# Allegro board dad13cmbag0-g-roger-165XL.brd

Outline 225 x 71 mm; copper layers: TOP, GND, IN1, IN2, SGND1, SVCC, IN3, IN4, GND2, BOTTOM. Coordinates in mm from the lower left corner of the outline.
Outline path: 0,6.1 0,17.14 arc(0.54,17.85) 1.06,18.58 arc(1.59,18.97) 2.26,18.94 arc(4.75,19.83) 4.19,22.41 arc(3.81,22.96) 3.87,23.62 arc(5.79,29.62) 6.44,35.9 6.44,59.4 arc(6.59,59.75) 6.94,59.9 10.44,59.9 10.44,68.4 arc(10.59,68.75) 10.94,68.9 14.54,68.9 arc(15.07,68.75) 15.44,68.33 arc(17.7,66.9) 19.96,68.33 arc(20.33,68.75) 20.86,68.9 63.6,68.9 65.7,71 73.7,71 75.8,68.9 118.54,68.9 arc(119.07,68.75) 119.44,68.33 arc(121.7,66.9) 123.96,68.33 arc(124.33,68.75) 124.86,68.9 204.9,68.9 206.41,70.41 arc(206.73,70.62) 207.11,70.7 209.71,70.7 arc(209.95,70.58) 209.99,70.32 arc(211.1,68.85) 212.21,70.32 arc(212.25,70.58) 212.49,70.7 213.88,70.7 arc(214.13,70.67) 214.37,70.57 arc(215.59,70.26) 216.8,70.57 arc(217.04,70.67) 217.29,70.7 222.8,70.7 arc(223.15,70.55) 223.3,70.2 223.3,69.9 arc(223.45,69.55) 223.8,69.4 224.5,69.4 arc(224.85,69.25) 225,68.9 225,67.25 arc(224.71,66.54) 224,66.25 215.05,66.25 214.98,66.24 214.92,66.21 214.87,66.17 214.83,66.12 214.81,66.06 214.8,66 214.81,65.93 214.83,65.87 214.87,65.82 214.93,65.78 214.99,65.76 215.05,65.75 215.05,58.05 214.98,58.04 214.92,58.01 214.87,57.97 214.83,57.92 214.81,57.86 214.8,57.8 214.81,57.73 214.83,57.67 214.87,57.62 214.93,57.58 214.99,57.56 215.05,57.55 224,57.55 arc(224.71,57.25) 225,56.55 225,53.75 214.64,53.75 214.64,54.25 212.4,54.25 212.4,39.15 214.64,39.15 214.64,39.65 223.3,39.65 223.3,34.9 224,34.9 224.4,34.5 224.4,30 225,29.4 225,27.2 224.5,27.2 224.5,26.2 225,26.2 225,23.6 224.5,23.6 224.5,22.6 225,22.6 225,20 224.5,20 224.5,19 225,19 225,16.4 224.5,16.4 224.5,15.4 225,15.4 225,12.85 224.5,12.85 224.5,11.85 225,11.85 225,9.7 arc(224.71,8.99) 224,8.7 214.2,8.7 arc(213.85,8.85) 213.7,9.2 213.7,10.83 arc(213.8,11.12) 214.05,11.3 arc(214.51,13.21) 212.6,12.75 arc(212.42,12.5) 212.13,12.4 210.9,12.4 arc(210.55,12.25) 210.4,11.9 210.4,8.4 arc(209.52,6.28) 207.4,5.4 129.62,5.4 arc(129.19,5.5) 128.84,5.77 arc(126.9,6.7) 124.96,5.77 arc(124.61,5.5) 124.18,5.4 54.5,5.4 arc(53.79,5.11) 53.5,4.4 53.5,2.8 arc(50.7,0) 47.9,2.8 47.9,4.4 arc(47.61,5.11) 46.9,5.4 15.32,5.4 arc(14.89,5.5) 14.54,5.77 arc(12.6,6.7) 10.66,5.77 arc(10.31,5.5) 9.88,5.4 9.5,5.4 8.5,5.1 1,5.1 arc(0.29,5.39) 0,6.1

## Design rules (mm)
constraint set DEFAULT: min track width 0.127
net group DFP-S4(4)W4(8)-1234: nets M_A_CLKN0 M_A_CLKP0
net group DFP-S4(4)W4(8)-T1234B: nets M_B_CLKN0 M_B_CLKP0
net group DFP-S4(5.5)W4(3.5)-T124B: nets CLK_PCIE_WLANN CLK_PCIE_WLANP
net group DFP-S6W10-T1234B: nets VCCSENSE VSSSENSE
net group DFP-S10(40)W30(40)-T1B: nets AUD_SPK_R+ AUD_SPK_R-
net group DFP-S10W5(3.5)-T123: nets I2C0_SCL_DSP I2C0_SDA_DSP
net group DFP-S10W10-T124B: nets REM_DIODE1_N REM_DIODE1_P
net group W3(3.5)-T1234B: nets M_A_ODT M_B_ODT
net group DFP-S3.5(4.5)W4.5(3.5)-T124B: nets PCIE_RXN3 PCIE_RXP3 PCIE_TXN3 PCIE_TXN3_C PCIE_TXP3 PCIE_TXP3_C USB3.0_RX1+ USB3.0_RX1- USB3.0_TX1+ USB3.0_TX1+_C USB3.0_TX1- USB3.0_TX1-_C
net group DFP-S4.5(4)W8.5(6.5)-T1234B: nets M_A_DQSN0 M_A_DQSN1 M_A_DQSN2 M_A_DQSN3 M_A_DQSN4 M_A_DQSN5 M_A_DQSN6 M_A_DQSN7 M_A_DQSP0 M_A_DQSP1 M_A_DQSP2 M_A_DQSP3 M_A_DQSP4 M_A_DQSP5 M_A_DQSP6 M_A_DQSP7 M_B_DQSN0 M_B_DQSN1 M_B_DQSN2 M_B_DQSN3 M_B_DQSN4 M_B_DQSN5 M_B_DQSN6 M_B_DQSN7 M_B_DQSP0 M_B_DQSP1 M_B_DQSP2 M_B_DQSP3 M_B_DQSP4 M_B_DQSP5 M_B_DQSP6 M_B_DQSP7
net group DFP-S5(8)W5.5(5)-T124B: nets AUX_SINK_N_R AUX_SINK_P_R EDP_AUXN EDP_AUXN_C EDP_AUXN_R EDP_AUXP EDP_AUXP_C EDP_AUXP_R EDP_TXN0_C EDP_TXN0_R EDP_TXN1 EDP_TXN1_C EDP_TXN1_R EDP_TXP0_C EDP_TXP0_R EDP_TXP1 EDP_TXP1_C EDP_TXP1_R INT_AUX_SINKN INT_AUX_SINKP INT_DP_TXN0 INT_DP_TXN1 INT_DP_TXN1_C INT_DP_TXN2 INT_DP_TXN3 INT_DP_TXN3_C INT_DP_TXP0 INT_DP_TXP1 INT_DP_TXP2 INT_DP_TXP3 INT_DP_TXP3_C
net group DFP-S5.5(6)W6.5(4.5)-T1234B: nets N123302860 N123302864 N123305105 N123305107
net group DFP-S5.5(9)W5(4.5)-T124B: nets SATA_RXN2_C SATA_RXP2_C SATA_TXN2_C SATA_TXP2_C USB3.0_RX2+ USB3.0_RX2- USB3.0_TX2+ USB3.0_TX2- USBP0+ USBP0+_L USBP0+_R USBP0- USBP0-_L USBP0-_R USBP1+ USBP1- USBP2+ USBP2+_R USBP2- USBP2-_R USBP4+ USBP4+_L USBP4- USBP4-_L USBP5+ USBP5+_L USBP5- USBP5-_L
net group DFP-S10W5(3.5)-T124B: nets DMIC_CLK DMIC_DATA PS/2_CLK_TPAD PS/2_DAT_TPAD SMB_CLK_ME1 SMB_DATA_ME1 SMBCLK SMBCLK0 SMBCLK0_B SMBCLK0_P SMBCLK1 SMBCLK3 SMBDAT0 SMBDAT0_B SMBDAT0_P SMBDAT1 SMBDAT3 SMBDATA TOUCH_PAD_CLK TOUCH_PAD_CLK_R TOUCH_PAD_DAT TOUCH_PAD_DAT_R TP_CLK TP_DATA
net group DFP-S10W5-TB: nets XTAL24_DSP_IN XTAL24_DSP_OUT XTAL24_IN XTAL24_OUT
net group T14B: nets USB_BIAS
net group T124B: nets SM_RCOMP_0 SM_RCOMP_1 SM_RCOMP_2
net group T1234B: nets +1.2V_SWR +1.2V_SWR_L +3.3V_DEEP_SLEEP_OFF +3.3V_RTC_LDO +DSP_VREF_IN +DVDD-25-LDO-O +DVDIO +LCDVCC +LED_BL +RTC_1 +RTC_CELL +SMDDR_VREF_CA +SMDDR_VREF_DQA +USB0_SIDE_PWR +V1.05DX_MODPHY +V1.05S_APLLOPI +V1.05S_ASATA3PLL +V1.05S_AUSB3PLL +V1.05S_AXCK_DCB +V1.05S_AXCK_LCPLL +V1.05S_VCCST +V3.3DX_1.5DX_AUDIO +V3.3DX_AUDIO +V3.3DX_CAMERA +V3.3DX_NGFF_WLAN +V3.3DX_SSD +V3.3S_1.8S_LPSS_SDIO +V5DX_AUDIO +VCCIO_OUT +VCCIOA_OUT PCIE_IREF PCIE_RCOMP SATA_RCOMP SM_VREF_CA SM_VREF_DQ0 SM_VREF_DQ1
net group TB: nets EDP_COMP PCH_OPIRCOMP PROC_OPI_COMP SATA_IREF
net group W3(6.5)-T1234B: nets M_A_A2 M_A_A5 M_A_A6 M_A_A8 M_A_A10 M_A_A11 M_A_A13 M_A_BS1 M_A_CKE0 M_A_CKE1 M_B_A2 M_B_A5 M_B_A6 M_B_A8 M_B_A10 M_B_A11 M_B_A12 M_B_A13 M_B_BS1 M_B_CKE0 M_B_CKE1
net group W5(3.5)-T123: nets SMC_EXTSMI_N
net group W5(3.5)-T124B: nets ACZ_SPKR APWROK BEEP BT_PCMCLK BT_PCMFR1 BT_PCMIN BT_PCMOUT BUF_PLT_RST# CLK_33M_TPM_TPM CLKDVCOM DP_UTIL DPWROK_R DSP_BITCLK DSP_BITCLK_R DSP_RST# DSP_SDIN0 DSP_SDOUT DSP_SYNC DSWVRMEN EC_SPI_CS# EC_SPI_DIN EC_SPI_DO EC_SPI_SLK H_CPU_SVIDALRT_N H_CPUPWRGD H_PROCHOT# H_PROCHOT#_EC HDA_BITCLK HDA_BITCLK_CODEC HDA_BITCLK_DSP HDA_BITCLK_R HDA_RST# HDA_RST#_CODEC HDA_RST#_DSP HDA_RST#_R HDA_SDIN0 HDA_SDIN0_CODEC HDA_SDIN0_DSP HDA_SDOUT HDA_SDOUT_CODEC HDA_SDOUT_DSP HDA_SDOUT_R HDA_SYNC HDA_SYNC_CODEC HDA_SYNC_DSP HDA_SYNC_R HWPG I2S_BCLK_OUT I2S_SDI_IN I2S_SDO_OUT I2S_SFRM_OUT IMVP7_PROCHOT# INT_DP_HPD INT_DP_HPD_R LCD_PWM LPC_CLK_0 LPC_CLK_1 LPC_CLK_DEBUG LPC_CLK_DEBUG_R LPC_CLK_EC LPC_CLK_TPM LPC_LAD0 LPC_LAD0_TPM LPC_LAD1 LPC_LAD1_TPM LPC_LAD2 LPC_LAD2_TPM LPC_LAD3 LPC_LAD3_TPM LPC_LFRAME# LPC_LFRAME#_TPM ME_SUS_PWR_ACK PCH_INTVRMEN PCH_PWROK PCH_SPI_CLK PCH_SPI_CS0# PCH_SPI_IO2 PCH_SPI_IO3 PCH_SPI_SI PCH_SPI_SO PCH_THRMTRIP# PCIE_WAKE# PCIE_WAKE#_R PECI_EC PECI_EC_R PLTRST# RSMRST# RTC_RST# SDIO_CMD SDIO_D0 SDIO_D1 SDIO_D2 SDIO_D3 SIO_PWRBTN# SIO_RCIN# SIO_SLP_LAN# SIO_WAKE_SCI# SM_INTRUDER# SPI_CS# SPI_SCK SPI_SI SPI_SO SRTC_RST# SYS_PWROK SYS_PWROK_R UART1_CTS UART1_CTS_R UART1_RTS UART1_RTS_R UART1_RX UART1_RX_R UART1_TX UART1_TX_R USB3_P0_EN USB3_P1_EN VCCST_PWRGD# VCCST_PWRGD_L VR_SVID_ALERT# VR_SVID_CLK VR_SVID_DATA XDP_TCK0 XDP_TCK1
net group W5(3.5)-T1234B: nets CFG0 CFG1 CFG2 CFG3 CFG4 CFG5 CFG6 CFG7 CFG8 CFG9 CFG10 CFG11 CFG12 CFG13 CFG14 CFG15 IRQ_SERIRQ NOA_RCOMP SIO_EXT_SCI# SIO_SLP_A# SIO_SLP_S3# SIO_SLP_S5# SUSACK# SUSACK#_R SYS_PWR_SW# SYS_RESET# SYS_SHDN# TD_IREF THERM_ALERT# THERM_STP# USB2_CAM_PWR_EN USB2_CAM_PWR_EN_R XDP_BPM0_R XDP_BPM1_R XDP_BPM2_R XDP_BPM3_R XDP_BPM4_R XDP_BPM5_R XDP_BPM6_R XDP_BPM7_R XDP_PRDY_N XDP_PREQ_N XDP_TDI_CPU XDP_TDO_CPU XDP_TMS_CPU XDP_TRST_CPU_N
net group W8.5(6)-T1234B: nets M_A_DQ0 M_A_DQ1 M_A_DQ2 M_A_DQ3 M_A_DQ4 M_A_DQ5 M_A_DQ6 M_A_DQ7 M_A_DQ8 M_A_DQ9 M_A_DQ10 M_A_DQ11 M_A_DQ12 M_A_DQ13 M_A_DQ14 M_A_DQ15 M_A_DQ16 M_A_DQ17 M_A_DQ18 M_A_DQ19 M_A_DQ20 M_A_DQ21 M_A_DQ22 M_A_DQ23 M_A_DQ24 M_A_DQ25 M_A_DQ26 M_A_DQ27 M_A_DQ28 M_A_DQ29 M_A_DQ30 M_A_DQ31 M_A_DQ32 M_A_DQ33 M_A_DQ34 M_A_DQ35 M_A_DQ36 M_A_DQ37 M_A_DQ38 M_A_DQ39 M_A_DQ40 M_A_DQ41 M_A_DQ42 M_A_DQ43 M_A_DQ44 M_A_DQ45 M_A_DQ46 M_A_DQ47 M_A_DQ48 M_A_DQ49 M_A_DQ50 M_A_DQ51 M_A_DQ52 M_A_DQ53 M_A_DQ54 M_A_DQ55 M_A_DQ56 M_A_DQ57 M_A_DQ58 M_A_DQ59 M_A_DQ60 M_A_DQ61 M_A_DQ62 M_A_DQ63 M_B_DQ0 M_B_DQ1 M_B_DQ2 M_B_DQ3 M_B_DQ4 M_B_DQ5 M_B_DQ6 M_B_DQ7 M_B_DQ8 M_B_DQ9 M_B_DQ10 M_B_DQ11 M_B_DQ12 M_B_DQ13 M_B_DQ14 M_B_DQ15 M_B_DQ16 M_B_DQ17 M_B_DQ18 M_B_DQ19 M_B_DQ20 M_B_DQ21 M_B_DQ22 M_B_DQ23 M_B_DQ24 M_B_DQ25 M_B_DQ26 M_B_DQ27 M_B_DQ28 M_B_DQ29 M_B_DQ30 M_B_DQ31 M_B_DQ32 M_B_DQ33 M_B_DQ34 M_B_DQ35 M_B_DQ36 M_B_DQ37 M_B_DQ38 M_B_DQ39 M_B_DQ40 M_B_DQ41 M_B_DQ42 M_B_DQ43 M_B_DQ44 M_B_DQ45 M_B_DQ46 M_B_DQ47 M_B_DQ48 M_B_DQ49 M_B_DQ50 M_B_DQ51 M_B_DQ52 M_B_DQ53 M_B_DQ54 M_B_DQ55 M_B_DQ56 M_B_DQ57 M_B_DQ58 M_B_DQ59 M_B_DQ60 M_B_DQ61 M_B_DQ62 M_B_DQ63
net group W9(6.5)-T1234B: nets M_A_A0 M_A_A1 M_A_A3 M_A_A4 M_A_A7 M_A_A9 M_A_A12 M_A_A14 M_A_A15 M_A_BS0 M_A_BS2 M_A_CAS# M_A_CS#0 M_A_CS#1 M_A_RAS# M_A_WE# M_B_A0 M_B_A1 M_B_A3 M_B_A4 M_B_A7 M_B_A9 M_B_A14 M_B_A15 M_B_BS0 M_B_BS2 M_B_CAS# M_B_CS#0 M_B_CS#1 M_B_RAS# M_B_WE# N123302883 N123302892 N123305111 N123305113

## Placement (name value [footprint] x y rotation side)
C1  10u/6.3v_6  [CC0603]  56.35 66.37 270 top
C2  47u/10v_8  [CC0805]  54.57 66.12 270 top
C3  0.1u/16v_4  [CC0402]  134.33 65.87 270 top
C4  0.1u/16v_4  [CC0402]  135.34 65.87 270 top
C5  1u/6.3v_4  [CC0402]  136.36 65.87 270 top
C6  0.1u/16v_4  [CC0402]  137.37 65.87 270 top
C7  0.1u/16v_4  [CC0402]  208.24 63.96 180 top
C8  100p/50v_4  [CC0402]  128.31 65.28 270 top
C9  *0.1u/10v_4_nc  [CC0402]  128.86 63.61 180 top
C10  0.1u/16v_4  [CC0402]  208.24 62.95 180 top
C11  47u/10v_8  [CC0805]  56.35 62.69 270 top
C12  10u/6.3v_6  [CC0603]  58 62.44 270 top
C13  0.1u/16v_4  [CC0402]  208.24 61.93 180 top
C14  0.1u/16v_4  [CC0402]  159.09 61.42 270 top
C15  0.1u/16v_4  [CC0402]  123.33 61.17 90 top
C16  0.1u/16v_4  [CC0402]  208.24 60.91 180 top
C17  1u/6.3v_4  [CC0402]  66.76 60.28 0 top
C18  1u/6.3v_4  [CC0402]  68.92 59.77 90 top
C19  1u/6.3v_4  [CC0402]  70.27 58.5 90 top
C20  0.1u/16v_4  [CC0402]  208.24 59.9 180 top
C21  22u/6.3v_6  [CC0603]  43.14 59.52 270 top
C22  22u/6.3v_6  [CC0603]  44.41 59.52 270 top
C23  22u/6.3v_6  [CC0603]  46.7 59.52 270 top
C24  22u/6.3v_6  [CC0603]  47.97 59.52 270 top
C25  22u/6.3v_6  [CC0603]  49.24 59.52 270 top
C26  100p/50v_4  [CC0402]  50.38 59.52 270 top
C27  10u/6.3v_6  [CC0603]  51.52 59.52 270 top
C28  22u/6.3v_6  [CC0603]  52.69 59.52 270 top
C29  22u/6.3v_6  [CC0603]  53.86 59.52 270 top
C30  10u/6.3v_6  [CC0603]  56.04 59.52 270 top
C31  22u/6.3v_6  [CC0603]  57.21 59.52 270 top
C32  22u/6.3v_6  [CC0603]  58.38 59.52 270 top
C33  22u/6.3v_6  [CC0603]  59.55 59.52 270 top
C34  10u/6.3v_6  [CC0603]  61.76 59.52 270 top
C35  22u/6.3v_6  [CC0603]  62.93 59.52 270 top
C36  100p/50v_4  [CC0402]  54.95 59.39 270 top
C37  100p/50v_4  [CC0402]  60.64 59.39 270 top
C38  100p/50v_4  [CC0402]  45.55 59.26 270 top
C39  1u/6.3v_4  [CC0402]  131.91 59.14 270 top
C40  1u/6.3v_4  [CC0402]  65.11 59.14 90 top
C41  2200p/50v_4  [CC0402]  150.45 58.37 90 top
C42  2200p/50v_4  [CC0402]  156.55 58.37 270 top
C43  0.1u/16v_4  [CC0402]  208.24 58.88 180 top
C44  0.1u/16v_4  [CC0402]  188.55 57.61 90 top
C45  0.1u/16v_4  [CC0402]  144.87 57.51 0 top
C46  22u/6.3v_6  [CC0603]  41.74 57.23 0 top
C47  1u/6.3v_4  [CC0402]  66.63 56.85 270 top
C48  10u/6.3v_6  [CC0603]  71.71 56.85 270 top
C49  22u/6.3v_6  [CC0603]  73.62 56.85 180 top
C50  10u/6.3v_6  [CC0603]  89.88 56.85 90 top
C51  47u/10v_8  [CC0805]  91.53 56.72 90 top
C52  22u/6.3v_6  [CC0603]  65.36 56.47 270 top
C53  0.1u/16v_4  [CC0402]  70.32 56.47 270 top
C54  0.1u/16v_4  [CC0402]  203.79 56.34 270 top
C55  0.1u/16v_4  [CC0402]  204.94 56.34 270 top
C56  0.1u/16v_4  [CC0402]  205.95 56.34 270 top
C57  22u/6.3v_6  [CC0603]  41.74 55.96 0 top
C58  1u/6.3v_4  [CC0402]  73.49 55.71 180 top
C59  22u/6.3v_6  [CC0603]  41.74 54.69 0 top
C60  1u/6.3v_4  [CC0402]  73.49 54.69 180 top
C61  1u/6.3v_4  [CC0402]  75.78 54.44 180 top
C62  10u/6.3v_6  [CC0603]  89.49 53.8 90 top
C63  0.1u/16v_4  [CC0402]  198.54 53.8 90 top
C64  1u/6.3v_4  [CC0402]  73.49 53.67 180 top
C65  22u/6.3v_6  [CC0603]  41.74 53.42 0 top
C66  47u/10v_8  [CC0805]  91.15 53.29 90 top
C67  0.1u/16v_4  [CC0402]  187.16 52.79 180 top
C68  1u/6.3v_4  [CC0402]  73.49 52.66 180 top
C69  0.1u/16v_4  [CC0402]  131.15 52.53 0 top
C70  22u/6.3v_6  [CC0603]  41.74 52.15 0 top
C71  0.1u/16v_4  [CC0402]  197.83 52.02 0 top
C72  0.1u/50v_6  [CC0603]  200.29 52.02 0 top
C73  22u/6.3v_6  [CC0603]  75.91 51.9 0 top
C74  *100p_nc  [CC0402]  52.71 51.82 270 top
C75  0.1u/50v_6  [CC0603]  203.54 51.26 90 top
C76  22u/6.3v_6  [CC0603]  41.74 50.88 0 top
C77  0.1u/16v_4  [CC0402]  192.49 50.88 0 top
C78  1u/6.3v_4  [CC0402]  75.65 50.75 180 top
C79  0.1u/16v_4  [CC0402]  73.49 50.5 0 top
C80  10u/6.3v_6  [CC0603]  89.49 50.12 270 top
C81  47u/10v_8  [CC0805]  91.15 49.86 270 top
C82  0.1u/16v_4  [CC0402]  135.47 49.86 90 top
C83  0.01u/25v_4  [CC0402]  170.14 49.86 180 top
C84  22u/6.3v_6  [CC0603]  41.74 49.61 0 top
C85  22u/6.3v_6  [CC0603]  75.91 49.61 0 top
C86  1u/6.3v_4  [CC0402]  73.49 49.48 0 top
C87  100u/6.3v/3216  [CC3216-0_9H]  34.38 49.36 0 top
C88  10u/6.3v_6  [CC0603]  202.14 48.98 270 top
C89  0.01u/25v_4  [CC0402]  170.14 48.72 180 top
C90  0.1u/16v_4  [CC0402]  203.29 48.72 270 top
C91  1u/6.3v_4  [CC0402]  73.87 48.47 180 top
C92  22u/6.3v_6  [CC0603]  41.74 48.34 0 top
C93  22u/6.3v_8  [CC0805]  206.97 47.71 180 top
C94  2200p/50v_4  [CC0402]  150.84 47.71 180 top
C95  0.1u/16v_4  [CC0402]  154.77 47.71 180 top
C96  1u/6.3v_4  [CC0402]  73.87 47.45 180 top
C97  *4.7u/6.3v_6_nc  [CC0603]  195.67 47.2 180 top
C98  22u/6.3v_6  [CC0603]  41.74 47.07 0 top
C99  0.1u/16v_4  [CC0402]  76.67 46.94 90 top
C100  0.1u/16v_4  [CC0402]  150.84 46.69 180 top
C101  2200p/50v_4  [CC0402]  154.77 46.69 180 top
C102  0.01u/25v_4  [CC0402]  170.27 46.69 0 top
C103  1u/6.3v_4  [CC0402]  68.67 46.56 270 top
C104  1u/6.3v_4  [CC0402]  69.68 46.56 90 top
C105  1u/6.3v_4  [CC0402]  70.7 46.56 270 top
C106  1u/6.3v_4  [CC0402]  71.71 46.56 90 top
C107  0.1u/10v_4  [CC0402]  195.92 45.93 180 top
C108  0.1u/16v_4  [CC0402]  84.97 45.67 90 top
C109  0.1u/16v_4  [CC0402]  85.99 45.67 90 top
C110  100u/6.3v/3216  [CC3216-0_9H]  40.73 45.55 180 top
C111  0.01u/25v_4  [CC0402]  170.27 45.55 0 top
C112  1u/6.3v_4  [CC0402]  65.34 45.42 90 top
C113  1u/6.3v_4  [CC0402]  67.37 45.42 90 top
C114  10u/6.3v_6  [CC0603]  51.27 41.86 180 top
C115  2.2u/6.3v_6  [CC0603]  53.68 44.15 90 top
C116  2.2u/6.3v_6  [CC0603]  56.6 45.29 90 top
C117  10u/6.3v_6  [CC0603]  53.55 36.91 0 top
C118  10u/6.3v_6  [CC0603]  58 35.51 180 top
C119  1u/6.3v_4  [CC0402]  77.3 44.53 90 top
C120  0.1u/16v_4  [CC0402]  68.54 44.2 270 top
C121  1u/6.3v_4  [CC0402]  69.56 44.2 270 top
C122  1u/6.3v_4  [CC0402]  70.57 44.2 270 top
C123  10u/6.3v_6  [CC0603]  71.84 44.05 270 top
C124  10p/50v_4  [CC0402]  103.34 43.64 270 top
C125  *100p_nc  [CC0402]  195.29 43.51 0 top
C126  0.1u/16v_4  [CC0402]  12.74 42.91 0 top
C127  22u/6.3v_8  [CC0805]  207.1 42.19 0 top
C128  18p/50v_4  [CC0402]  109.05 41.86 0 top
C129  18p/50v_4  [CC0402]  111.08 41.86 0 top
C130  *100p_nc  [CC0402]  198.08 41.36 270 top
C131  *100p_nc  [CC0402]  199.1 41.36 270 top
C132  2200p/50v_4  [CC0402]  11.82 41.33 90 top
C133  10p/50v_4  [CC0402]  105.5 41.23 270 top
C134  4.7u/6.3v_4  [CC0402]  112.86 41.1 270 top
C135  0.1u/16v_4  [CC0402]  113.88 41.1 270 top
C136  10u/6.3v_6  [CC0603]  58 38.31 180 top
C137  10p/50v_4  [CC0402]  106.51 40.97 270 top
C138  10p/50v_4  [CC0402]  107.53 40.97 270 top
C139  0.1u/16v_4  [CC0402]  96.86 39.32 0 top
C140  *0.1u/10v_4_nc  [CC0402]  92.54 38.94 90 top
C141  10u/6.3v_6  [CC0603]  112.02 38.69 270 top
C142  *0.1u/25v_6_nc  [CC0603]  113.17 38.69 90 top
C143  0.1u/16v_4  [CC0402]  114.26 38.36 270 top
C144  4.7u/6.3v_4  [CC0402]  96.86 38.31 0 top
C145  0.047u/10v_4  [CC0402]  180.17 37.51 180 top
C146  0.1u/16v_4  [CC0402]  100.8 37.42 0 top
C147  1u/6.3v_4  [CC0402]  161.48 37.06 270 top
C148  10u/6.3v_6  [CC0603]  98.38 37.16 0 top
C149  0.047u/10v_4  [CC0402]  180.17 36.5 180 top
C150  0.1u/16v_4  [CC0402]  100.8 36.02 0 top
C151  0.1u/16v_4  [CC0402]  112.23 36.02 270 top
C152  10u/6.3v_6  [CC0603]  113.62 35.89 270 top
C153  4.7u/6.3v_6  [CC0603]  179.92 35.35 180 top
C154  10u/6.3v_6  [CC0603]  97.75 35.26 270 top
C155  10u/6.3v_6  [CC0603]  99.02 35.26 270 top
C156  47p/50v_4  [CC0402]  138.52 34.75 90 top
C157  0.1u/16v_4  [CC0402]  113.8 34.09 0 top
C158  0.1u/16v_4  [CC0402]  112.15 33.58 90 top
C159  0.1u/10v_4  [CC0402]  170.52 32.6 0 top
C160  0.1u/16v_4  [CC0402]  112.66 31.93 180 top
C161  1u/6.3v_4  [CC0402]  71.71 31.35 90 top
C162  1u/6.3v_4  [CC0402]  75.55 31.35 90 top
C163  1u/6.3v_4  [CC0402]  198.79 31.32 90 top
C164  4.7u/6.3v_4  [CC0402]  112.66 30.92 180 top
C165  0.1u/16v_4  [CC0402]  101.31 30.89 0 top
C166  4.7u/6.3v_4  [CC0402]  102.7 29.8 0 top
C167  0.1u/16v_4  [CC0402]  191.35 19.89 270 top
C168  2200p/50v_4  [CC0402]  15.71 19.64 270 top
C169  *100p_nc  [CC0402]  16.85 19.64 270 top
C170  0.047u/10v_4  [CC0402]  32.6 18.24 0 top
C171  0.047u/10v_4  [CC0402]  76.54 17.99 180 top
C172  0.047u/10v_4  [CC0402]  44.79 17.35 180 top
C173  0.047u/10v_4  [CC0402]  64.22 17.48 0 top
C174  0.047u/10v_4  [CC0402]  20.25 17.48 0 top
C175  0.047u/10v_4  [CC0402]  53.68 17.86 0 top
C176  0.047u/10v_4  [CC0402]  99.91 17.58 180 top
C177  0.047u/10v_4  [CC0402]  88.48 16.72 90 top
C178  1u/6.3v_4  [CC0402]  86.07 12.27 180 top
C179  0.047u/10v_4  [CC0402]  61.05 16.08 0 top
C180  1u/6.3v_4  [CC0402]  219.16 16.08 180 top
C181  0.047u/10v_4  [CC0402]  83.4 13.54 180 top
C182  10u/6.3v_6  [CC0603]  68.29 10.62 0 top
C183  1u/6.3v_4  [CC0402]  85.68 7.57 90 top
C184  0.047u/10v_4  [CC0402]  26.63 14.69 0 top
C185  0.047u/10v_4  [CC0402]  39.08 13.92 90 top
C186  0.047u/10v_4  [CC0402]  51.9 13.92 180 top
C187  0.047u/10v_4  [CC0402]  70.95 12.65 0 top
C188  1u/6.3v_4  [CC0402]  40.98 19 270 top
C189  1u/6.3v_4  [CC0402]  39.58 10.88 180 top
C190  0.047u/10v_4  [CC0402]  95.08 13.8 90 top
C191  0.047u/10v_4  [CC0402]  16.37 12.98 90 top
C192  1u/6.3v_4  [CC0402]  71.08 9.22 0 top
C193  1u/6.3v_4  [CC0402]  67.14 14.3 270 top
C194  1u/6.3v_4  [CC0402]  32.55 14.66 180 top
C195  1u/6.3v_4  [CC0402]  27.14 17.48 0 top
C196  *0.1u/25v_6_nc  [CC0603]  103.08 11.89 0 top
C197  1u/6.3v_4  [CC0402]  70.95 10.49 0 top
C198  1u/6.3v_4  [CC0402]  86.07 10.24 180 top
C199  1u/6.3v_4  [CC0402]  26.88 7.83 90 top
C200  10u/6.3v_6  [CC0603]  25.23 7.95 90 top
C201  1u/6.3v_4  [CC0402]  81.24 16.59 180 top
C202  1u/6.3v_4  [CC0402]  70.95 11.51 0 top
C203  1u/6.3v_4  [CC0402]  39.58 8.84 180 top
C204  1u/6.3v_4  [CC0402]  26.63 13.54 0 top
C205  *10u/6.3v_6_nc  [CC0603]  87.21 7.83 90 top
C206  1u/6.3v_4  [CC0402]  26.88 11.26 0 top
C207  1u/6.3v_4  [CC0402]  78.83 26.5 0 bottom
C208  1u/6.3v_4  [CC0402]  90.13 26.5 0 bottom
C209  *10u/6.3v_6_nc  [CC0603]  42.25 18.75 270 top
C210  1u/6.3v_4  [CC0402]  36.03 27.13 270 bottom
C211  1u/6.3v_4  [CC0402]  74.25 7.7 90 bottom
C212  1u/6.3v_4  [CC0402]  102.07 16.34 90 bottom
C213  1u/6.3v_4  [CC0402]  31.96 27.13 270 bottom
C214  1u/6.3v_4  [CC0402]  80.99 26.5 180 bottom
C215  1u/6.3v_4  [CC0402]  85.3 26.5 180 bottom
C216  1u/6.3v_4  [CC0402]  13.17 9.22 0 bottom
C217  1u/6.3v_4  [CC0402]  44.03 7.83 90 bottom
C218  1u/6.3v_4  [CC0402]  85.68 7.83 90 bottom
C219  1u/6.3v_4  [CC0402]  91.53 7.83 90 bottom
C220  1u/6.3v_4  [CC0402]  94.45 26.5 180 bottom
C221  1u/6.3v_4  [CC0402]  83.14 26.5 180 bottom
C222  1u/6.3v_4  [CC0402]  67.78 26.62 180 bottom
C223  1u/6.3v_4  [CC0402]  96.61 26.5 0 bottom
C224  1u/6.3v_4  [CC0402]  34 27.13 270 bottom
C225  1u/6.3v_4  [CC0402]  46.31 7.83 90 bottom
C226  1u/6.3v_4  [CC0402]  102.07 18.5 90 bottom
C227  1u/6.3v_4  [CC0402]  62.57 26.62 180 bottom
C228  1u/6.3v_4  [CC0402]  35.01 27.13 270 bottom
C229  1u/6.3v_4  [CC0402]  32.98 7.83 90 bottom
C230  1u/6.3v_4  [CC0402]  45.17 7.83 90 bottom
C231  1u/6.3v_4  [CC0402]  32.98 27.13 270 bottom
C232  1u/6.3v_4  [CC0402]  92.29 26.5 180 bottom
C233  1u/6.3v_4  [CC0402]  77.43 7.83 90 bottom
C234  1u/6.3v_4  [CC0402]  31.84 7.83 90 bottom
C235  1u/6.3v_4  [CC0402]  88.61 7.83 90 bottom
C236  1u/6.3v_4  [CC0402]  75.65 65.61 270 bottom
C237  12p/50v_4  [CC0402]  64.09 66.25 0 bottom
C238  47u/10v_8  [CC0805]  77.35 66.12 270 bottom
C239  10u/6.3v_6  [CC0603]  74.89 67.26 0 bottom
C240  0.1u/16v_4  [CC0402]  56.86 65.74 270 bottom
C241  0.1u/16v_4  [CC0402]  57.87 65.74 270 bottom
C242  12p/50v_4  [CC0402]  64.09 64.98 0 bottom
C243  0.1u/16v_4  [CC0402]  206.08 62.42 180 bottom
C244  0.1u/16v_4  [CC0402]  206.08 61.33 180 bottom
C245  0.1u/16v_4  [CC0402]  207.07 59.16 0 bottom
C246  *10u/6.3v_6_nc  [CC0603]  207.48 57.99 180 bottom
C247  0.1u/16v_4  [CC0402]  98.64 52.66 0 bottom
C248  0.1u/16v_4  [CC0402]  189.32 49.48 90 bottom
C249  0.1u/16v_4  [CC0402]  190.34 49.48 90 bottom
C250  0.1u/16v_4  [CC0402]  191.35 49.48 90 bottom
C251  0.1u/16v_4  [CC0402]  192.37 49.48 90 bottom
C252  0.1u/16v_4  [CC0402]  186.27 48.47 90 bottom
C253  0.1u/16v_4  [CC0402]  187.29 48.47 90 bottom
C254  *1.6p/50v_4_nc  [CC0402]  202.96 43.12 90 bottom
C255  0.1u/16v_4  [CC0402]  198.46 42.88 180 bottom
C256  0.1u/16v_4  [CC0402]  198.46 43.9 180 bottom
C257  *1.6p/50v_4_nc  [CC0402]  202.96 45.15 270 bottom
C258  10u/6.3v_6  [CC0603]  169.5 42.5 270 bottom
C259  0.1u/16v_4  [CC0402]  23.33 41.86 0 bottom
C260  *100u/10v_3528_nc  [CC3528]  212.3 35.01 270 bottom
C261  15p/50v_4  [CC0402]  83.25 35.39 90 bottom
C262  *0.1u/16v_4_nc  [CC0402]  56.6 8.21 90 bottom
C263  10u/6.3v_6  [CC0603]  53.17 33.99 90 bottom
C264  2.2u/6.3v_6  [CC0603]  54.44 33.99 90 bottom
C265  10u/6.3v_6  [CC0603]  44.79 35.39 0 bottom
C266  2.2u/6.3v_6  [CC0603]  59.65 45.29 90 top
C267  15p/50v_4  [CC0402]  83.25 33.35 270 bottom
C268  1u/6.3v_4  [CC0402]  219.54 30.94 270 bottom
C269  330u/2.5v/e15/3528  [CC3528]  39.71 27.64 0 bottom
C270  0.022u/16v_4  [CC0402]  30.82 27.13 90 bottom
C271  0.022u/16v_4  [CC0402]  55.84 27.13 90 bottom
C272  0.022u/16v_4  [CC0402]  72.73 26.75 90 bottom
C273  1u/6.3v_4  [CC0402]  221.75 26.5 180 bottom
C274  0.1u/16v_4  [CC0402]  169.63 21.92 180 bottom
C275  0.047u/10v_4  [CC0402]  159.22 19.51 180 bottom
C276  1u/6.3v_4  [CC0402]  219.54 19.51 90 bottom
C277  0.1u/16v_4  [CC0402]  159.22 18.5 180 bottom
C278  0.1u/16v_4  [CC0402]  181.44 15.83 0 bottom
C279  0.1u/16v_4  [CC0402]  183.47 15.83 180 bottom
C280  1u/6.3v_4  [CC0402]  221.57 15.07 180 bottom
C281  0.1u/16v_4  [CC0402]  146.59 9.22 270 bottom
C282  10u/6.3v_6  [CC0603]  60.16 26.62 0 bottom
C283  10u/6.3v_6  [CC0603]  42.83 8.06 90 bottom
C284  10u/6.3v_6  [CC0603]  99.4 7.95 90 bottom
C285  1u/6.3v_4  [CC0402]  37.19 7.95 90 bottom
C286  10u/6.3v_6  [CC0603]  38.52 7.93 90 bottom
C287  1u/6.3v_4  [CC0402]  40.9 7.93 90 bottom
C288  1u/6.3v_4  [CC0402]  15.73 7.85 90 bottom
C289  1u/6.3v_4  [CC0402]  68.02 7.83 90 bottom
C290  1u/6.3v_4  [CC0402]  78.56 7.83 90 bottom
C291  10u/6.3v_6  [CC0603]  21.68 7.83 90 bottom
C292  1u/6.3v_4  [CC0402]  23.45 7.83 90 bottom
C293  10u/6.3v_6  [CC0603]  26.88 7.83 90 bottom
C294  1u/6.3v_4  [CC0402]  29.3 7.83 90 bottom
C295  1u/6.3v_4  [CC0402]  30.69 7.83 90 bottom
C296  1u/6.3v_4  [CC0402]  52.28 7.83 90 bottom
C297  10u/6.3v_6  [CC0603]  53.81 7.83 90 bottom
C298  10u/6.3v_6  [CC0603]  87.72 26.62 0 bottom
C299  1u/6.3v_4  [CC0402]  63.33 7.83 90 bottom
C300  1u/6.3v_4  [CC0402]  66.13 7.83 90 bottom
C301  1u/6.3v_4  [CC0402]  73.03 7.72 90 bottom
C302  10u/6.3v_6  [CC0603]  81.87 7.95 90 bottom
C303  1u/6.3v_4  [CC0402]  83.78 7.83 90 bottom
C304  1u/6.3v_4  [CC0402]  94.07 7.83 90 bottom
C305  1u/6.3v_4  [CC0402]  95.97 7.83 90 bottom
C306  1u/6.3v_4  [CC0402]  98 7.83 90 bottom
C307  1u/6.3v_4  [CC0402]  17.74 7.8 90 bottom
C308  10u/6.3v_6  [CC0603]  71.18 7.8 90 bottom
C309  1u/6.3v_4  [CC0402]  50.63 7.83 90 bottom
C310  1u/6.3v_4  [CC0402]  61.17 7.7 90 bottom
C311  10u/6.3v_6  [CC0603]  87.26 7.78 90 bottom
C312  10u/6.3v_6  [CC0603]  65.24 26.62 0 bottom
C313  1u/6.3v_4  [CC0402]  20.23 7.57 90 bottom
C525  *0.47u/6.3v_4_nc  [CC0402]  66.35 45.42 270 top
C526  0.1u/16v_4  [CC0402]  35.19 17.2 0 top
C527  0.1u/16v_4  [CC0402]  76.54 19 0 top
CN1  2my3003-000111f  [DP-3V112M1-RC5AA1-7H-20P]  216.1 61.9 270 bottom
CN2  yusb0011-p001a  [USB-YUSB0011-P001A-10P]  219.05 46.7 270 bottom
CN3  yea-btb-055-p01  [YEA-BTB-055-P01-54P-LDH-SMT]  16.4 35 180 bottom
CN4  sm3zs067u215ae  [MINIPCI-SM3ZS067U215AE-75P-KE]  178.2 28.15 270 bottom
CN5  50281-00201-001  [88266-0200-2P-L]  215.1 27.07 180 bottom
CN6  50503-0060n-001  [88513-0601-6P-L-SMT]  194.35 13.85 180 bottom
CN7  50278-0050n-001  [50278-0050N-001-5P-L]  5.53 11.4 90 bottom
CON1  51700-0520w-001  [MIPCI-800055FB052GX00PL-52P-SMT]  163.13 48.65 270 bottom
D1  sdmk0340l-7-f  [DSMV]  145.88 62.06 90 top
D2  bat54cw  [UMT_213-3-1_3]  120.61 60.91 270 top
D3  bat54cw  [UMT_213-3-1_3]  125.82 60.66 180 top
D4  sdmk0340l-7-f  [DSMV]  145.88 60.28 90 top
D5  bat54cw  [UMT_213-3-1_3]  125.77 56.85 270 top
D6  *sdmk0340l-7-f_nc  [DSMV]  129.5 55.96 180 top
D7  bat54cw  [UMT_213-3-1_3]  119.21 55.76 270 top
D8  sdmk0340l-7-f  [DSMV]  194.65 55.45 180 top
D9  bat54cw  [UMT_213-3-1_3]  190.33 54.56 0 top
D10  *sdmk0340l-7-f_nc  [DSMV]  94.32 52.4 270 top
D11  *sdmk0340l-7-f_nc  [DSMV]  94.32 50.63 270 top
D12  sdmk0340l-7-f  [DSMV]  136.87 49.1 180 top
D13  sdmk0340l-7-f  [DSMV]  131.28 48.85 0 top
D14  sdmk0340l-7-f  [DSMV]  133.06 48.85 0 top
D15  sdmk0340l-7-f  [DSMV]  138.64 48.72 0 top
D16  sdmk0340l-7-f  [DSMV]  140.42 48.72 0 top
D18  bat54cw  [UMT_213-3-1_3]  201.33 31.07 270 top
D19  ltw-270tla  [LEDLTW-270TLA]  223.94 24.9 270 top
D20  ltw-270tla  [LEDLTW-270TLA]  223.94 21.3 270 top
D21  ltw-270tla  [LEDLTW-270TLA]  223.94 17.7 270 top
D22  ltw-270tla  [LEDLTW-270TLA]  223.94 14.1 270 top
D23  ltw-270tla  [LEDLTW-270TLA]  223.94 10.5 270 top
D24  bat54cw  [UMT_213-3-1_3]  192.36 41.36 180 bottom
D25  bat54cw  [UMT_213-3-1_3]  166.33 44.4 90 top
DPF1  1206l150thwr  [F-3_2X1_65-3_68]  207.5 54.18 90 bottom
EC1  *10p/50v_4_nc  [CC0402]  153.5 58.37 90 top
EC2  *10p/50v_4_nc  [CC0402]  80.25 50.5 0 top
EC3  *10p/50v_4_nc  [CC0402]  70.06 41.18 180 top
EC4  *10p/50v_4_nc  [CC0402]  68.03 40.59 0 top
EC5  0.1u/25v_4  [CC0402]  142.86 33.02 0 top
EC6  47p/50v_4  [CC0402]  99.37 33.3 0 top
EC7  2200p/50v_4  [CC0402]  158.33 32.21 180 top
EC8  2200p/50v_4  [CC0402]  142.86 31.86 0 top
EC9  0.1u/25v_4  [CC0402]  158.33 31.2 180 top
EC10  10p/50v_4  [CC0402]  154.52 23.7 270 top
EC11  10p/50v_4  [CC0402]  155.53 23.7 270 top
EC12  *10p/50v_4_nc  [CC0402]  7.33 23.7 0 top
EC13  1000p/50v_4  [CC0402]  121.78 21.87 270 top
EC14  0.1u/25v_4  [CC0402]  120.61 21.85 270 top
EC15  0.1u/25v_4  [CC0402]  131.28 22.18 180 top
EC16  68p/50v_4  [CC0402]  7.33 21.42 0 top
EC17  2200p/50v_4  [CC0402]  131.28 21.04 180 top
EC18  100p/25v_2  [CC0201]  141.44 20.83 90 top
EC19  100p/25v_2  [CC0201]  142.45 20.83 90 top
EC20  100p/25v_2  [CC0201]  143.52 20.83 90 top
EC21  4700p/50v_4  [CC0402]  7.33 20.27 0 top
EC22  *33p/16v/4_nc  [CC0402]  192.36 19.89 270 top
EC23  *33p/16v/4_nc  [CC0402]  193.51 19.89 270 top
EC24  *33p/16v/4_nc  [CC0402]  194.65 19.89 270 top
EC25  *33p/16v/4_nc  [CC0402]  195.79 19.89 270 top
EC26  *33p/16v/4_nc  [CC0402]  196.94 19.89 270 top
EC27  0.01u/25v_4  [CC0402]  7.33 19.13 0 top
EC28  100p/25v_2  [CC0201]  140.93 18.37 90 top
EC29  100p/25v_2  [CC0201]  142 18.37 90 top
EC30  100p/25v_2  [CC0201]  142.94 18.37 90 top
EC31  100p/25v_2  [CC0201]  143.9 18.37 90 top
EC32  100p/25v_2  [CC0201]  144.84 18.37 90 top
EC33  100p/25v_2  [CC0201]  145.83 18.37 90 top
EC34  100p/25v_2  [CC0201]  146.8 18.37 90 top
EC35  100p/25v_2  [CC0201]  147.76 18.37 90 top
EC36  100p/25v_2  [CC0201]  148.7 18.37 90 top
EC37  100p/25v_2  [CC0201]  149.72 18.37 90 top
EC38  100p/25v_2  [CC0201]  150.71 18.37 90 top
EC39  100p/25v_2  [CC0201]  151.72 18.37 90 top
EC40  100p/25v_2  [CC0201]  152.69 18.37 90 top
EC41  100p/25v_2  [CC0201]  153.65 18.37 90 top
EC42  100p/25v_2  [CC0201]  154.72 18.37 90 top
EC43  100p/25v_2  [CC0201]  155.74 18.37 90 top
EC44  100p/25v_2  [CC0201]  156.75 18.37 90 top
EC45  100p/25v_2  [CC0201]  157.77 18.37 90 top
EC46  100p/25v_2  [CC0201]  158.79 18.37 90 top
EC47  100p/25v_2  [CC0201]  159.8 18.37 90 top
EC48  100p/25v_2  [CC0201]  160.82 18.37 90 top
EC49  100p/25v_2  [CC0201]  161.83 18.37 90 top
EC50  2200p/50v_4  [CC0402]  109.05 65.89 270 bottom
EC51  0.1u/25v_4  [CC0402]  110.22 65.87 270 bottom
EC52  0.1u/25v_4  [CC0402]  16.8 60.99 180 bottom
EC53  2200p/50v_4  [CC0402]  16.82 59.85 180 bottom
EC54  100p/50v_4  [CC0402]  179.33 49.76 90 bottom
EC55  100p/50v_4  [CC0402]  182.48 49.76 90 bottom
EC56  100p/50v_4  [CC0402]  20.79 39.2 270 bottom
EC57  100p/50v_4  [CC0402]  21.8 39.2 270 bottom
EC58  *0.1u/16v_4_nc  [CC0402]  22.82 39.2 270 bottom
EC59  *10p/50v_4_nc  [CC0402]  70.75 32.97 0 bottom
EC60  100p/50v_4  [CC0402]  214.02 31.53 0 bottom
EC61  100p/50v_4  [CC0402]  216.18 31.53 0 bottom
EC62  100p/50v_4  [CC0402]  8.98 31.32 0 bottom
EC63  100p/50v_4  [CC0402]  20.41 30.81 90 bottom
EC64  *0.1u/16v_4_nc  [CC0402]  21.42 30.81 90 bottom
EC65  100p/50v_4  [CC0402]  11.64 31.32 180 bottom
EC66  0.1u/25v_4  [CC0402]  187.54 8.59 180 bottom
EC68  100p/50v_4  [CC0402]  14.89 30.54 0 bottom
EC69  0.1u/25v_4  [CC0402]  12.53 63.45 0 bottom
EC70  0.1u/25v_4  [CC0402]  124.95 8.67 90 bottom
EC71  0.1u/25v_4  [CC0402]  118.27 66.27 180 bottom
EC72  0.1u/25v_4  [CC0402]  22.82 63.71 180 bottom
EC73  0.1u/25v_4  [CC0402]  150.45 31.07 90 top
EC74  0.1u/25v_4  [CC0402]  123.66 13.8 270 top
EC75  0.01u/25v_4  [CC0402]  122.26 13.8 270 top
EC76  0.01u/25v_4  [CC0402]  21.42 66.37 270 bottom
EC77  0.01u/25v_4  [CC0402]  13.17 60.15 270 top
EC78  0.1u/25v_4  [CC0402]  12.15 60.15 270 top
EC79  0.01u/25v_4  [CC0402]  12.53 64.47 0 bottom
EC80  4700p/50v_4  [CC0402]  10.22 22.56 270 bottom
EL1  dlp11sn900hl2l  [CHOKE-DLP11SN900HL2L-4P-1]  203.67 45.04 270 top
EL2  dlp11sn900hl2l  [CHOKE-DLP11SN900HL2L-4P-1]  183.86 49.23 0 bottom
EL3  dlp11sn900hl2l  [CHOKE-DLP11SN900HL2L-4P-1]  189.96 47.2 180 bottom
EL4  dlp11sn900hl2l  [CHOKE-DLP11SN900HL2L-4P-1]  191.86 47.2 180 bottom
EL6  dlp11sn900hl2l  [CHOKE-DLP11SN900HL2L-4P-1]  186.78 46.18 180 bottom
EL8  dlp11sn900hl2l  [CHOKE-DLP11SN900HL2L-4P-1]  170.27 36.7 90 bottom
EL9  dlp11sn900hl2l  [CHOKE-DLP11SN900HL2L-4P-1]  145.32 17.05 270 bottom
ESD1  *tvl st23 04 ad0_nc  [TSOP6-2_8-95]  206.97 45.04 180 top
ESD2  *tvl st23 04 ad0_nc  [TSOP6-2_8-95]  109.33 16.69 180 top
ESD3  *tvl st23 04 ad0_nc  [TSOP6-2_8-95]  141.9 17.59 0 bottom
EU1  esd7004mutag  [UDFN10-2_5X1-5]  205.06 46.18 90 bottom
FL1  blm11b102s (1k,100ma)  [RC0603]  6.74 11.26 0 top
FL2  mhc2012s800ubp(80,5a)  [RC0805]  8.54 22.76 270 bottom
FS1  1206l050yr  [FSMD1206P150TS]  165.97 21.52 180 bottom
H1  *h-tc166bc177ic131d91p2_nc  [H-TC166BC177IC131D91P2]  211.1 70 0 top
H2  *h-c79d79n_nc  [H-C79D79N]  219.8 68.8 0 top
H3  *h-tc197bc220ic131d91p2_nc  [H-TC197BC220IC131D91P2]  69.7 68.2 0 top
H4  h-tc217bc197d102p2  [H-TC217BC197D102P2]  33.7 63.7 180 bottom
H5  h-tc217ic142bc197d102p2  [H-TC217IC142BC197D102P2]  83.7 63.7 180 bottom
H6  h-tc217ic142bc197d102p2  [H-TC217IC142BC197D102P2]  33.7 40.9 180 bottom
H7  h-tc217ic142bc197d102p2  [H-TC217IC142BC197D102P2]  83.7 40.9 180 bottom
H8  h-c217ic142d102pt  [H-C217IC142D102PT]  206.45 28.15 180 bottom
H9  *h-tic217bc220d91p2_nc  [H-TIC217BC220D91P2]  136.3 20.9 0 top
H10  *h-tc197bc220ic131d91p2_nc  [H-TC197BC220IC131D91P2]  213.7 12.4 0 top
H11  *h-o79x87d79x87n_nc  [H-O79X87D79X87N]  219.8 10.8 0 top
H12  h-c220d142p2  [H-C220D142P2]  50.7 2.8 0 top
H13  h-tc217bc197ic142d102p2  [H-TC217BC197IC142D102P2]  115 60.75 180 bottom
H14  fbd13019  [PAD-M14-1]  199.7 45.15 180 bottom
J1  gs12401-1011p-7h  [GS12401-1011-40P-R-NH-SMT]  192.6 54.37 0 bottom
J2  50519-00401-001  [91504-0401-4P-L]  165.45 15.82 180 bottom
JBAT1  24-01209-001  [GS73091-10272-7H-9P-LUV_AB]  110.7 7.82 0 bottom
JKB1  50699-03041-001  [50699-03001-001-30P-L]  149.9 12.55 0 top
JP1  50503-0080n-001  [88513-0801-8P-L]  153.05 18.35 180 bottom
JP2  50208-00801-001  [88460-08XX-8P-L]  142.55 11.19 90 bottom
L1  fcm1608kf-121t02  [RC0603]  144.87 58.75 180 top
L2  fcm1608kf-121t02  [RC0603]  144.87 56.34 0 top
L3  4.7uh (lqm2hpn4r7mg0l)  [L3_2X2_5-1_55]  99.91 39.32 180 top
L4  fcm1608kf-601t02  [RC0603]  149.47 20.65 90 bottom
L5  fcm1608kf-601t02  [RC0603]  150.62 20.65 90 bottom
L6  2.2uh_8  [RC0805]  54.32 62.69 90 top
L7  2.2uh_8  [RC0805]  79.38 66.12 90 bottom
L8  2.2uh_8  [RC0805]  94.32 54.44 0 top
L9  2.2uh_8  [RC0805]  52.41 66.12 90 top
L10  2.2uh_8  [RC0805]  94.32 57.36 0 top
L11  2.2uh_8  [RC0805]  96.1 47.71 0 top
NOREF  -  []  35.93 27.28 0 top
NOREF#2  -  []  118.26 -22.6 0 top
NOREF#3  -  [unnamed#2]  2.37 7.32 0 top
NOREF#4  -  [unnamed#2]  194.9 7.57 0 top
NOREF#5  -  []  202.09 11.31 0 top
NOREF#6  -  []  54.93 29.83 0 top
NOREF#7  -  [unnamed#2]  13.04 66.5 0 top
NOREF#8  -  []  67.46 -62.73 0 top
NOREF#9  -  [unnamed#2]  194.9 7.57 180 bottom
NOREF#10  -  [unnamed#2]  13.04 66.5 180 bottom
NOREF#11  -  []  134.32 48.46 180 bottom
NOREF#12  -  []  153.25 46.49 180 bottom
NOREF#13  -  [unnamed#2]  204.81 65.74 180 bottom
NOREF#14  -  []  198.16 63.63 180 bottom
PC1  1000p/50v_4  [CC0402]  188.07 65.77 90 top
PC2  *1000p/50v_4_nc  [CC0402]  102.19 65.61 270 top
PC3  2.2u/6.3v_4  [CC0402]  186.29 59.64 180 top
PC4  1000p/50v_4  [CC0402]  181.7 57.94 90 top
PC5  0.22u/10v_4  [CC0402]  183.4 57.38 0 top
PC6  0.1u/25v_4  [CC0402]  98 53.67 0 top
PC7  2200p/50v_4  [CC0402]  99.53 53.17 270 top
PC8  2200p/50v_4  [CC0402]  100.54 53.17 270 top
PC9  0.1u/25v_4  [CC0402]  102.19 52.66 180 top
PC10  0.1u/25v_4  [CC0402]  125.69 52.28 270 top
PC11  470p/50v_4  [CC0402]  122.51 52.23 270 top
PC12  470p/50v_4  [CC0402]  123.66 52.23 270 top
PC13  2.2u/6.3v_4  [CC0402]  16.22 52.02 270 top
PC14  1u/6.3v_4  [CC0402]  102.7 50.12 180 top
PC15  0.01u/16v_4  [CC0402]  97.24 49.86 270 top
PC16  0.1u/25v_4  [CC0402]  119.72 48.72 90 top
PC17  1u/6.3v_4  [CC0402]  120.74 48.72 270 top
PC18  470p/50v_4  [CC0402]  189.95 48.49 270 top
PC19  470p/50v_4  [CC0402]  190.97 48.49 270 top
PC20  1u/6.3v_4  [CC0402]  126.07 47.71 180 top
PC21  *4700p/25v_4_nc  [CC0402]  141.82 47.71 270 top
PC22  0.1u/25v_4  [CC0402]  99.65 47.32 90 top
PC23  0.1u/25v_4  [CC0402]  163.28 47.45 180 top
PC24  0.01u/25v_4  [CC0402]  102.7 47.07 180 top
PC25  470p/50v_4  [CC0402]  157.67 46.41 0 top
PC26  1u/6.3v_4  [CC0402]  95.74 46.05 0 top
PC27  0.01u/16v_4  [CC0402]  122.01 45.93 90 top
PC28  0.1u/25v_4  [CC0402]  123.15 45.93 90 top
PC29  0.01u/16v_4  [CC0402]  124.17 45.93 90 top
PC30  0.1u/25v_4  [CC0402]  193.15 45.93 180 top
PC31  0.1u/25v_4  [CC0402]  187.51 45.8 0 top
PC32  0.1u/25v_4  [CC0402]  157.67 45.39 0 top
PC33  0.01u/16v_4  [CC0402]  130.52 45.17 0 top
PC34  1u/6.3v_4  [CC0402]  101.18 44.4 90 top
PC35  1u/6.3v_4  [CC0402]  162.77 43.77 90 top
PC36  1u/6.3v_4  [CC0402]  187.92 43.9 270 top
PC37  1u/6.3v_4  [CC0402]  192.75 43.9 270 top
PC38  0.1u/25v_4  [CC0402]  142.02 43.24 90 top
PC39  *0.22u/6.3v_4_nc  [CC0402]  125.05 43.13 0 top
PC40  100p/50v_4  [CC0402]  127.09 43.13 0 top
PC41  *0.22u/6.3v_4_nc  [CC0402]  125.05 42.12 0 top
PC42  0.01u/16v_4  [CC0402]  127.09 42.12 0 top
PC43  0.1u/25v_4  [CC0402]  144.31 41.53 0 top
PC44  0.1u/25v_4  [CC0402]  139.07 41.51 180 top
PC45  0.1u/25v_4  [CC0402]  141.82 41.48 180 top
PC46  0.1u/25v_4  [CC0402]  190.33 41.36 90 top
PC47  1u/6.3v_4  [CC0402]  155.56 40.95 180 top
PC48  *0.047u/10v_4_nc  [CC0402]  119.85 40.85 90 top
PC49  0.1u/25v_4  [CC0402]  164.68 40.85 270 top
PC50  470p/50v_4  [CC0402]  165.69 41.46 270 top
PC51  470p/50v_4  [CC0402]  166.71 41.46 270 top
PC52  0.1u/25v_4  [CC0402]  167.73 40.85 270 top
PC53  0.01u/16v_4  [CC0402]  136.87 40.75 180 top
PC54  0.01u/16v_4  [CC0402]  127.09 40.09 0 top
PC55  100p/50v_4  [CC0402]  127.04 39.07 0 top
PC56  0.01u/16v_4  [CC0402]  130.08 39.07 0 top
PC57  0.1u/25v_4  [CC0402]  136.53 38.94 90 top
PC58  0.1u/25v_6  [CC0603]  146.84 38.38 180 top
PC59  0.1u/25v_6  [CC0603]  155.86 38.38 0 top
PC60  100p/50v_4  [CC0402]  130.08 38.05 0 top
PC61  0.047u/25v_4  [CC0402]  193.99 37.75 180 top
PC62  10u/6.3v_6  [CC0603]  196.48 37.75 0 top
PC63  33n/10v_4  [CC0402]  123.4 37.47 180 top
PC64  1u/6.3v_4  [CC0402]  115.78 36.83 0 top
PC65  1u/6.3v_4  [CC0402]  169.76 36.48 180 top
PC66  0.1u/25v_4  [CC0402]  140.68 36.4 0 top
PC67  0.1u/25v_4  [CC0402]  142.83 36.4 180 top
PC68  100p/50v_4  [CC0402]  127.98 35.89 270 top
PC69  0.01u/25v_4  [CC0402]  130.01 35.89 270 top
PC70  4.7u/6.3v_4  [CC0402]  153.43 35.74 180 top
PC71  1u/6.3v_4  [CC0402]  191.65 35.67 0 top
PC72  22u/6.3v_6  [CC0603]  124.29 35.51 90 top
PC73  0.1u/25v_4  [CC0402]  150.4 35.01 270 top
PC74  10u/6.3v_6  [CC0603]  199.07 34.65 270 top
PC75  *10u/6.3v_6_nc  [CC0603]  200.39 34.65 270 top
PC76  10u/6.3v_6  [CC0603]  152.94 34.5 180 top
PC77  1u/6.3v_4  [CC0402]  163.89 34.24 90 top
PC78  0.1u/25v_4  [CC0402]  167.09 34.09 90 top
PC79  *0.1u/16v_4_nc  [CC0402]  196.68 33.15 0 top
PC80  *10u/6.3v_6_nc  [CC0603]  120.71 32.54 90 top
PC81  0.1u/50v_6  [CC0603]  118.07 32.52 270 top
PC82  0.1u/25v_4  [CC0402]  123.86 29.67 90 top
PC83  0.1u/25v_4  [CC0402]  124.34 31.32 0 top
PC84  0.1u/25v_4  [CC0402]  93.81 31.32 270 top
PC85  0.1u/25v_4  [CC0402]  124.88 29.67 90 top
PC86  0.1u/25v_4  [CC0402]  133.44 30.69 180 top
PC87  0.1u/25v_4  [CC0402]  131.91 30.18 90 top
PC88  1u/6.3v_4  [CC0402]  97.5 30.05 0 top
PC89  470p/50v_4  [CC0402]  93.3 29.67 0 top
PC90  0.1u/25v_4  [CC0402]  133.44 29.67 180 top
PC91  0.1u/25v_4  [CC0402]  191.92 29.46 270 top
PC92  *2200p/50v_4_nc  [CC0402]  140.68 28.78 180 top
PC93  *2200p/50v_4_nc  [CC0402]  160.61 28.78 180 top
PC94  470p/50v_4  [CC0402]  93.3 28.66 0 top
PC95  1u/10v_6  [CC0603]  125.28 27.89 0 top
PC96  1u/25v_6  [CC0603]  129.78 27.11 270 top
PC97  0.047u/25v_4  [CC0402]  128.56 26.93 270 top
PC98  0.1u/25v_4  [CC0402]  99.4 26.88 180 top
PC99  1u/6.3v_4  [CC0402]  189 26.84 90 top
PC100  1u/6.3v_4  [CC0402]  193.64 26.84 90 top
PC101  *2200p/50v_4_nc  [CC0402]  115.07 26.7 90 top
PC102  0.1u/25v_4  [CC0402]  95.34 25.4 180 top
PC103  1u/6.3v_4  [CC0402]  97.37 25.4 0 top
PC104  0.1u/25v_4  [CC0402]  203.79 23.58 270 top
PC105  470p/50v_4  [CC0402]  192.54 22.41 90 top
PC106  0.1u/25v_4  [CC0402]  193.57 22.85 90 top
PC107  470p/50v_4  [CC0402]  191.04 22.41 90 top
PC108  0.1u/25v_4  [CC0402]  190.01 22.8 90 top
PC109  1u/6.3v_4  [CC0402]  201.38 22.69 180 top
PC110  0.1u/25v_4  [CC0402]  121.75 19.77 270 top
PC111  0.01u/16v_4  [CC0402]  198.59 21.42 0 top
PC112  470p/50v_4  [CC0402]  205.72 21.14 180 top
PC113  0.1u/25v_4  [CC0402]  198.59 20.4 0 top
PC114  470p/50v_4  [CC0402]  205.7 19.97 180 top
PC115  0.01u/16v_4  [CC0402]  198.59 19.38 0 top
PC116  0.1u/25v_4  [CC0402]  168.87 19 270 top
PC117  470p/50v_4  [CC0402]  169.89 19.05 270 top
PC118  470p/50v_4  [CC0402]  171.03 19.05 270 top
PC119  1u/6.3v_4  [CC0402]  202.14 18.06 180 top
PC120  0.1u/25v_4  [CC0402]  203.79 17.56 90 top
PC121  0.1u/25v_4  [CC0402]  173.36 16.46 180 top
PC122  1000p/50v_4  [CC0402]  130.54 14.51 0 top
PC123  1u/25v_6  [CC0603]  132.72 14.48 270 top
PC124  1u/6.3v_4  [CC0402]  168.21 14.48 270 top
PC125  1u/6.3v_4  [CC0402]  172.91 14.36 270 top
PC126  2200p/50v_4  [CC0402]  116.16 14.15 0 top
PC127  1000p/50v_4  [CC0402]  116.16 13.03 0 top
PC128  0.1u/25v_4  [CC0402]  116.14 11.82 0 top
PC129  0.1u/25v_4  [CC0402]  170.62 11.69 90 top
PC130  100p/50v_4  [CC0402]  6.33 10.04 180 top
PC131  10u/16v_8  [CC0805]  173.21 66.25 180 bottom
PC132  *15u/25v/e100/3528_nc  [CC3528]  25.56 65.94 180 bottom
PC133  10u/16v_8  [CC0805]  111.9 65.64 270 bottom
PC134  10u/16v_8  [CC0805]  114.06 65.64 270 bottom
PC135  *15u/25v/e100/3528_nc  [CC3528]  127.82 65.56 180 bottom
PC136  22u/6.3v_6  [CC0603]  90.64 65.49 270 bottom
PC137  22u/6.3v_6  [CC0603]  88.02 65.46 270 bottom
PC138  22u/6.3v_6  [CC0603]  89.34 65.46 270 bottom
PC139  22u/6.3v_6  [CC0603]  91.93 65.46 270 bottom
PC140  22u/6.3v_6  [CC0603]  93.25 65.46 270 bottom
PC141  0.1u/25v_4  [CC0402]  159.34 65.23 90 bottom
PC142  0.1u/25v_4  [CC0402]  88.53 63.45 0 bottom
PC143  1500p/50v_4  [CC0402]  29.3 63.33 90 bottom
PC144  2.2u/10v_6  [CC0603]  109.81 62.67 180 bottom
PC145  0.15u/10v_4  [CC0402]  23.33 62.06 180 bottom
PC146  0.1u/25v_4  [CC0402]  169.5 61.78 90 bottom
PC147  0.01u/50v_4  [CC0402]  185.76 61.55 270 bottom
PC148  10u/16v_8  [CC0805]  14.67 61.02 270 bottom
PC149  10u/16v_8  [CC0805]  12.53 60.99 270 bottom
PC150  *2200p/50v_4_nc  [CC0402]  23.33 60.91 180 bottom
PC151  *100p/50v_4_nc  [CC0402]  28.79 60.79 180 bottom
PC152  0.01u/50v_4  [CC0402]  109.61 60.13 180 bottom
PC153  1000p/50v_4  [CC0402]  19.64 59.77 0 bottom
PC154  4700p/50v_4  [CC0402]  19.64 58.75 0 bottom
PC155  0.33u/6.3v_4  [CC0402]  28.79 58.75 180 bottom
PC156  0.22u/6.3v_4  [CC0402]  107.02 58.5 180 bottom
PC157  0.1u/25v_6  [CC0603]  100.44 58.37 270 bottom
PC158  0.1u/25v_4  [CC0402]  16.98 58.12 270 bottom
PC159  10u/16v_8  [CC0805]  9.92 57.89 0 bottom
PC160  1u/6.3v_4  [CC0402]  28.79 57.74 180 bottom
PC161  2.2u/100v_1206  [CC3_5X1_7]  172.55 55.55 0 bottom
PC162  1u/6.3v_4  [CC0402]  26.5 52.4 90 bottom
PC163  0.1u/25v_4  [CC0402]  29.55 52.4 270 bottom
PC164  2.2u/100v_1206  [CC3_5X1_7]  172.55 52.18 0 bottom
PC165  100u/16v/e50/7343  [CC7343]  9.46 51.44 270 bottom
PC166  22u/6.3v_6  [CC0603]  21.68 48.87 270 bottom
PC167  22u/6.3v_6  [CC0603]  22.95 48.87 270 bottom
PC168  22u/6.3v_6  [CC0603]  24.12 48.88 270 bottom
PC169  22u/6.3v_6  [CC0603]  25.3 48.88 270 bottom
PC170  1000p/50v_4  [CC0402]  11.21 45.5 90 bottom
PC171  22u/6.3v_6  [CC0603]  21.68 44.91 90 bottom
PC172  22u/6.3v_6  [CC0603]  22.95 44.91 90 bottom
PC173  22u/6.3v_6  [CC0603]  24.13 44.9 90 bottom
PC174  22u/6.3v_6  [CC0603]  25.31 44.91 90 bottom
PC175  0.1u/25v_4  [CC0402]  26.98 44.15 180 bottom
PC176  *0.1u/25v_4_nc  [CC0402]  94.96 38.18 270 bottom
PC177  *1000p/50v_4_nc  [CC0402]  92.69 33.48 90 bottom
PC178  *0.1u/25v_4_nc  [CC0402]  93.71 33.48 90 bottom
PC179  *0.01u/16v_4_nc  [CC0402]  96.76 33.48 90 bottom
PC180  *1u/6.3v_4_nc  [CC0402]  99.02 32.97 180 bottom
PC181  220u/6.3v/e25_3528  [CC3528]  137.12 29.54 270 bottom
PC182  10u/16v_8  [CC0805]  148.57 28.55 90 bottom
PC183  10u/16v_8  [CC0805]  150.76 28.55 90 bottom
PC184  10u/16v_8  [CC0805]  152.92 28.53 90 bottom
PC185  10u/16v_8  [CC0805]  155.08 28.53 90 bottom
PC186  220u/6.3v/e25_3528  [CC3528]  165.41 28.31 270 bottom
PC187  10u/16v_8  [CC0805]  121.75 28.25 270 bottom
PC188  10u/16v_8  [CC0805]  119.62 28.22 270 bottom
PC189  0.1u/25v_4  [CC0402]  167.47 27.77 270 bottom
PC190  220u/2.5v/e15_3528  [CC3528]  104.23 26.78 90 bottom
PC191  0.01u/16v_4  [CC0402]  148.93 25.35 90 bottom
PC192  100p/50v_4  [CC0402]  149.95 25.35 90 bottom
PC193  0.1u/16v_4  [CC0402]  102.04 25.02 90 bottom
PC194  0.1u/25v_4  [CC0402]  119.11 24.97 90 bottom
PC195  2200p/50v_4  [CC0402]  120.28 24.97 90 bottom
PC196  10u/25v_8  [CC0805]  131.2 23.6 180 bottom
PC197  0.01u/16v_4  [CC0402]  155.28 23.58 180 bottom
PC198  0.01u/16v_4  [CC0402]  148.93 23.32 270 bottom
PC199  100p/50v_4  [CC0402]  149.95 23.32 270 bottom
PC200  0.1u/25v_4  [CC0402]  6.79 22.99 90 bottom
PC201  100p/50v_4  [CC0402]  155.28 22.56 180 bottom
PC202  10u/25v_8  [CC0805]  131.25 21.21 180 bottom
PC203  2200p/50v_4  [CC0402]  7.33 20.53 0 bottom
PC204  1000p/50v_4  [CC0402]  7.33 19.51 0 bottom
PC205  0.1u/25v_4  [CC0402]  145.19 19.16 180 bottom
PC206  1u/25v_6  [CC0603]  124.29 19 90 bottom
PC207  0.1u/25v_4  [CC0402]  7.33 18.5 0 bottom
PC208  1u/25v_6  [CC0603]  122.64 17.35 270 bottom
PC209  0.047u/25v_4  [CC0402]  183.98 13.16 270 bottom
PC210  *22p/50v_4_nc  [CC0402]  187.54 12.65 0 bottom
PC211  1u/6.3v_4  [CC0402]  187.54 9.73 180 bottom
PC212  10u/16v_8  [CC0805]  123.3 8.92 90 bottom
PC213  10u/16v_8  [CC0805]  121.14 8.89 90 bottom
PC214  22u/6.3v_6  [CC0603]  171.72 8.62 90 bottom
PC215  22u/6.3v_6  [CC0603]  173.03 8.62 90 bottom
PC216  0.1u/25v_4  [CC0402]  170.44 8.54 90 bottom
PC217  10u/6.3v_6  [CC0603]  187.54 7.32 180 bottom
PC218  *0.1u/25v_4_nc  [CC0402]  44.41 65.99 0 top
PC219  10u/16v_8  [CC0805]  20.15 64.22 0 bottom
PD1  bas16tw  [SOT363-2_1-65-6P]  132.55 41.61 270 top
PD2  bat54sw-7-f  [UMT_213-3-1_3]  143.46 38.92 90 top
PD3  bat54sw-7-f  [UMT_213-3-1_3]  139.86 38.89 90 top
PD4  1ss355  [DSMV]  133.59 26.4 180 top
PD5  sdm10k45-7-f  [DSMV]  127.01 24.92 270 top
PD6  da204ugt106  [UMT_213-3-1_3]  7.22 13.31 180 top
PD7  1ss355  [DSMV]  130.41 9.81 0 top
PD8  ss20100fl  [D-SOD-123FL-2_8X1_8]  172.35 58.25 0 bottom
PD9  *sdmk0340l-7-f_nc  [DSMV]  45.81 64.47 90 top
PL1  0.33uh (tmpc0603h-r33mg-d)  [CHOKE-MPLC0730L3R3]  98.18 63.33 180 bottom
PL2  10uh (#a915ay-h-100m=p3)  [CHOKE-A915AY-H-100M]  172.96 62.11 270 bottom
PL3  0.24uh (etqp4lr24afm)  [CHOKE-PCMC063T-R82MN-4P-SMT]  16.47 47.45 0 bottom
PL4  1uh (pcmc063t-1r0mn)  [CHOKE-MPLC0730L3R3]  110.04 27.13 0 bottom
PL5  3.3uh (tmpc0603h-3r3mg-d)  [CHOKE-MPLC0730L3R3]  159.98 24.57 270 bottom
PL6  3.3uh (tmpc0603h-3r3mg-d)  [CHOKE-MPLC0730L3R3]  143.72 24.34 90 bottom
PL7  2.2uh (tmpc0603h-2r2mg-d)  [CHOKE-MPLC0730L3R3]  129.52 11.97 270 bottom
PL8  2.2uh (fdv0530s-h-2r2m=p3)  [CHOKE-PCMB053T-1R0MS]  177.68 9.43 0 bottom
PQ1  dmn66d0ldw-7  [SOT-363]  131.4 56.09 90 top
PQ2  dmn66d0ldw-7  [SOT-363]  144.15 49.94 180 top
PQ3  2n7002w  [UMT_213-3-1_3]  105.67 49.08 0 top
PQ4  ao3409  [SOT23_213-3_3-2]  109.69 48.42 270 top
PQ5  fdc8886  [SSOT6-2_8-95]  144.49 46.56 90 top
PQ6  dmn66d0ldw-7  [SOT-363]  105.8 46.54 0 top
PQ7  dmn66d0ldw-7  [SOT-363]  151.47 44.94 0 top
PQ8  2n7002w  [UMT_213-3-1_3]  134.45 44.66 180 top
PQ9  rq3e150bnfu7tb  [PG-TSDSON-8-8P-R]  98.77 43.41 180 top
PQ10  *2n7002w_nc  [UMT_213-3-1_3]  133.31 36.02 0 top
PQ11  2n7002w  [UMT_213-3-1_3]  136.61 35.34 90 top
PQ12  2n7002w  [UMT_213-3-1_3]  9.99 20.15 270 top
PQ13  mmst3904-7-f  [UMT_213-3-1_3]  3.59 16.26 0 top
PQ14  dmn66d0ldw-7  [SOT-363]  134.49 13.72 270 top
PQ15  fdv301n_g  [SOT23_213-3_3-2]  3.31 10.75 180 top
PQ16  bc856b  [SOT23_123-2_37-1_9-1_11H]  133.13 9.61 180 top
PQ17  ao3409  [SOT23_213-3_3-2]  162.16 65.69 180 bottom
PQ18  2n7002w  [UMT_213-3-1_3]  154.72 65.54 180 bottom
PQ19  csd97374q4m  [SON8-4_5X3_5-5-9P]  14.69 53.8 180 bottom
PQ20  fdmc7692s  [PG-TSDSON-8-8P-R]  140.8 30.69 180 bottom
PQ21  fdmc8884  [PG-TSDSON-8-8P-R]  145.63 30.69 0 bottom
PQ22  fdmc8884  [PG-TSDSON-8-8P-R]  158 30.69 0 bottom
PQ23  fdmc8884  [PG-TSDSON-8-8P-R]  161.81 30.69 180 bottom
PQ24  fdmc0310as  [PG-TSDSON-8-8P-R]  116.16 30.33 90 bottom
PQ25  fdmc7696  [PG-TSDSON-8-8P-R]  116.16 25.94 180 bottom
PQ26  rq3e070bnfu7tb  [PG-TSDSON-8-8P-R]  124.09 22.31 270 bottom
PQ27  rq3e070bnfu7tb  [PG-TSDSON-8-8P-R]  120.1 21.57 90 bottom
PQ28  fdmc7678  [PG-TSDSON-8-8P-R]  131.28 18.24 0 bottom
PQ29  fdmc7678  [PG-TSDSON-8-8P-R]  127.26 18.19 270 bottom
PQ30  fdmc4435bz  [PG-TSDSON-8-8P-R]  120.15 17.68 0 bottom
PQ31  2n7002w  [UMT_213-3-1_3]  152.49 27.13 270 top
PQ32  2n7002w  [UMT_213-3-1_3]  8.6 16.84 0 top
PR1  21.5k/f_4  [RC0402]  179.79 66.63 270 top
PR2  *sj0402_nc  [SHORT0402]  181.06 66.63 90 top
PR3  *sj0402_nc  [SHORT0402]  182.08 66.63 90 top
PR4  *sj0402_nc  [SHORT0402]  183.73 66.63 90 top
PR5  *sj0402_nc  [SHORT0402]  184.74 66.63 90 top
PR6  300k/f_4  [RC0402]  189.24 65.77 90 top
PR7  10k/f_4  [RC0402]  190.41 65.77 270 top
PR8  *2.2_8_nc  [RC0805]  99.86 65.61 0 top
PR9  10k/f_4  [RC0402]  186.37 65.43 180 top
PR10  53.6k/f_4  [RC0402]  176.74 63.25 0 top
PR11  10k/f_4  [RC0402]  186.37 64.27 0 top
PR12  100k/f_4  [RC0402]  186.32 63.1 180 top
PR13  1m/f_4  [RC0402]  176.74 62.23 180 top
PR14  100k_4  [RC0402]  186.32 61.96 0 top
PR15  39k/f_4  [RC0402]  19.39 60.91 0 top
PR16  *100k_4_nc  [RC0402]  186.27 60.79 180 top
PR17  *10k/f_4_nc  [RC0402]  19.39 59.77 0 top
PR18  10k/f_4  [RC0402]  183.4 58.55 180 top
PR19  10_6  [RC0603]  28.41 58.5 270 top
PR20  75k/f_4  [RC0402]  18.88 58.12 270 top
PR21  412k/f_4  [RC0402]  20.03 58.12 90 top
PR22  150k/f_4  [RC0402]  19.39 56.34 0 top
PR24  54.9/f_4  [RC0402]  28.79 55.45 0 top
PR25  75k/f_4  [RC0402]  19.39 55.2 0 top
PR26  100k_4  [RC0402]  131.4 53.55 180 top
PR27  10_6  [RC0603]  26.76 52.66 180 top
PR31  100k_4  [RC0402]  146.8 49.92 270 top
PR32  *sj0402_nc  [SHORT0402]  95.72 49.23 0 top
PR33  1.5k_4  [RC0402]  102.7 49.1 0 top
PR34  *sj0805_nc  [SHORT0805]  192.49 48.59 270 top
PR35  *sj0805_nc  [SHORT0805]  188.3 48.21 270 top
PR36  330_4  [RC0402]  102.7 48.09 0 top
PR37  10k_4  [RC0402]  112.58 46.66 0 top
PR38  *sj0402_nc  [SHORT0402]  163.28 46.44 180 top
PR39  100_4  [RC0402]  102.7 45.93 180 top
PR40  *sj0402_nc  [SHORT0402]  119.72 45.93 90 top
PR41  *100k_4_nc  [RC0402]  120.86 45.93 90 top
PR42  *100k_4_nc  [RC0402]  125.18 45.93 90 top
PR44  100k_4  [RC0402]  141.44 45.93 180 top
PR45  100k_4  [RC0402]  163.28 45.42 180 top
PR46  *sj0603_nc  [SHORT0603]  157.69 44.28 0 top
PR47  100k_4  [RC0402]  104.4 44.38 270 top
PR48  *sj0402_nc  [SHORT0402]  105.42 44.38 90 top
PR49  *10k_4_nc  [RC0402]  106.44 44.38 90 top
PR50  *sj0402_nc  [SHORT0402]  119.09 44.28 0 top
PR51  1.5m_4  [RC0402]  129.5 44.15 0 top
PR52  *sj0402_nc  [SHORT0402]  131.53 44.15 0 top
PR53  64.9k/f_4  [RC0402]  148.55 43.39 180 top
PR54  150k/f_4  [RC0402]  154.14 43.39 0 top
PR55  *10k_4_nc  [RC0402]  119.47 43.13 180 top
PR56  *0_8_nc  [RC0805]  144.41 43.24 0 top
PR57  215k/f_4  [RC0402]  150.2 42.88 270 top
PR58  100k/f_4  [RC0402]  151.34 42.88 270 top
PR59  249k/f_4  [RC0402]  152.49 42.88 270 top
PR61  100k/f_4  [RC0402]  148.55 42.37 0 top
PR62  100k/f_4  [RC0402]  154.14 42.37 180 top
PR63  *100k_4_nc  [RC0402]  137.37 42.27 90 top
PR65  *sj0805_nc  [SHORT0805]  170.27 41.61 180 top
PR66  *sj0402_nc  [SHORT0402]  118.32 41.48 180 top
PR67  *sj0402_nc  [SHORT0402]  188.3 41.36 90 top
PR68  10k_4  [RC0402]  189.32 41.36 90 top
PR69  10k_4  [RC0402]  191.35 41.36 90 top
PR70  *sj0402_nc  [SHORT0402]  192.36 41.36 270 top
PR71  100k/f_4  [RC0402]  125.05 41.1 0 top
PR72  47.5k/f_4  [RC0402]  127.09 41.1 180 top
